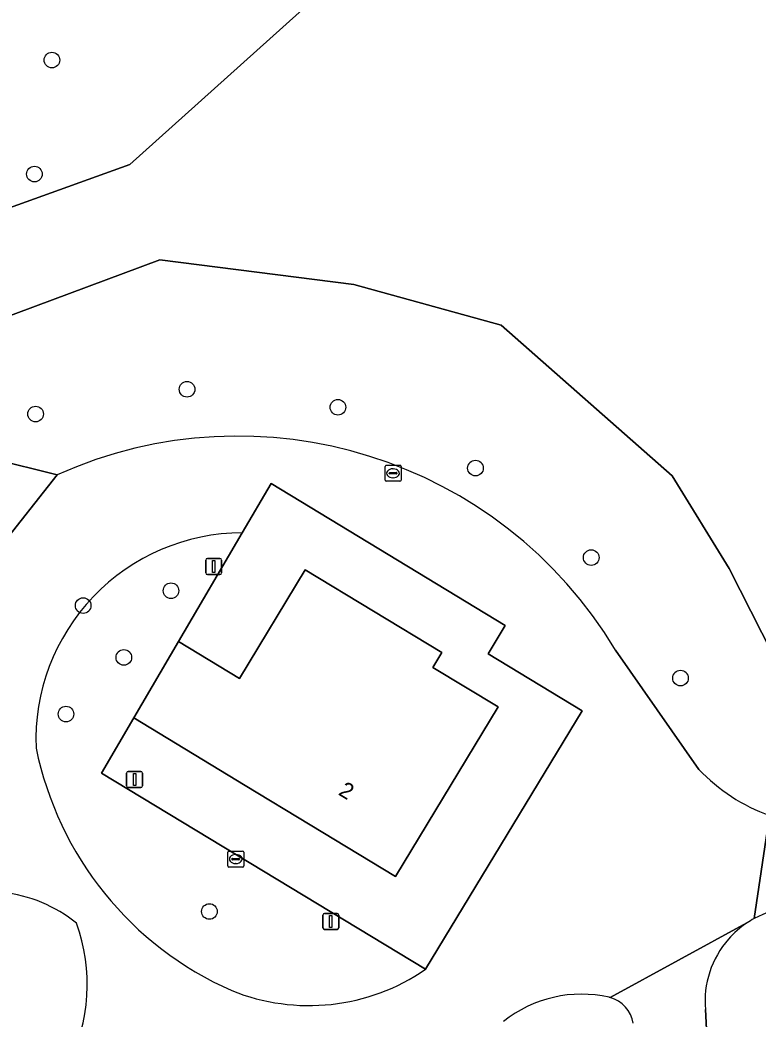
# Model space of a CAD drawing. Extents: x 157132 to 159279, y 384991 to 386650.
# Drawn here: x 158963.1 to 159009.3, y 385274.6 to 385337.1 of the extents above; entities that cross this region are included whole.
import ezdxf

# ---------------------------------------------------------------- set-up
doc = ezdxf.new("R2010")
doc.units = 0
for name, color, linetype in [('IMGEO_Boom', 7, 'Continuous'), ('IMGEO_Erf', 7, 'Continuous'), ('IMGEO_Gemengd_bos', 7, 'Continuous'), ('IMGEO_Groenvoorziening', 7, 'Continuous'), ('IMGEO_Lichtmast', 7, 'Continuous'), ('IMGEO_Pand', 7, 'Continuous'), ('IMGEO_Pand_nummerreeks', 7, 'Continuous'), ('IMGEO_Rioolput', 7, 'Continuous'), ('IMGEO_Voetpad_halfverhard', 7, 'Continuous')]:
    doc.layers.add(name, color=color, linetype=linetype)

msp = doc.modelspace()

# ---------------------------------------------------------------- linework, layer by layer
at = {"layer": 'IMGEO_Boom'}
for centre in [(158965.128, 385334.634), (158964.034, 385327.492), (158973.584, 385314.015), (158983.029, 385312.89), (158964.106, 385312.467), (158991.637, 385309.08), (158998.879, 385303.476), (158972.581, 385301.402), (158967.084, 385300.47), (158969.63, 385297.223), (159004.469, 385295.927), (158966.009, 385293.676), (158974.984, 385281.314)]:
    msp.add_circle(centre, 0.489, dxfattribs=at)
at = {"layer": 'IMGEO_Erf'}
msp.add_lwpolyline([(158978.843, 385308.107), (158977.039, 385305.028), (158973.048, 385298.218), (158976.862, 385295.907), (158980.986, 385302.716), (158989.536, 385297.535), (158988.971, 385296.602), (158993.067, 385294.121), (158986.637, 385283.507), (158981.292, 385286.745), (158977.231, 385289.205), (158970.246, 385293.436), (158968.224, 385289.986), (158988.516, 385277.692), (158998.324, 385293.883), (158992.431, 385297.452), (158993.504, 385299.223)], close=True, dxfattribs=at)
at = {"layer": 'IMGEO_Gemengd_bos'}
for points in [[(159000.067, 385275.929), (159000, 385275.946)], [(159006.024, 385275.17), (159006.37, 385268.533), (159008.379, 385268.484), (159009.307, 385250), (159010.121, 385233.765), (159038.341, 385217.156), (159039.121, 385218.285)]]:
    msp.add_lwpolyline(points, dxfattribs=at)
for centre, radius, start, end in [((158961.135, 385273.769), 8.778, 50.89459, 84.10287), ((159011.929, 385275.665), 5.936, 94.97558, 118.8036), ((159012.182, 385275.253), 6.418, 119.01394, 123.60203), ((158956.077, 385276.751), 11.266, 332.96541, 19.87475), ((159011.896, 385275.706), 5.883, 123.71788, 138.74506), ((159011.933, 385275.676), 5.931, 138.76669, 184.89371), ((158998.28, 385268.26), 7.876, 77.38908, 128.39246), ((158999.536, 385274.017), 1.985, 8.53143, 74.48901)]:
    msp.add_arc(centre, radius, start, end, dxfattribs=at)
at = {"layer": 'IMGEO_Groenvoorziening'}
for points in [[(158962.808, 385385.31), (158927.58, 385336.09), (158925.528, 385331.856), (158955.073, 385313.584), (158959.489, 385317.515), (158971.873, 385322.123), (158984.027, 385320.568), (158993.243, 385318.034), (159003.957, 385308.587), (159007.514, 385302.784), (159015.678, 385286.714), (159042.69, 385289.202), (159041.339, 385291.519)], [(159007.514, 385302.784), (159003.957, 385308.587), (158993.243, 385318.034), (158984.027, 385320.568), (158971.873, 385322.123), (158959.489, 385317.515), (158955.073, 385313.584), (158958.196, 385311.653), (158961.42, 385309.659), (158965.458, 385308.659)], [(158968.224, 385289.986), (158970.246, 385293.436), (158973.048, 385298.218), (158977.039, 385305.028)], [(159015.678, 385286.714), (159007.514, 385302.784)], [(159000.4, 385297.684), (159005.617, 385290.211)], [(158988.516, 385277.692), (158968.224, 385289.986)]]:
    msp.add_lwpolyline(points, dxfattribs=at)
for points in [[(158974.969, 385377.175), (158969.67, 385375.217), (158966.329, 385370.263), (158969.324, 385358.052), (158963.794, 385345.265), (158951.929, 385334.09), (158951.929, 385329.597), (158952.044, 385325.335), (158955.961, 385323.031), (158970.015, 385328.099), (158981.42, 385338.352), (158985.452, 385352.753), (158981.996, 385373.259)], [(158981.42, 385338.352), (158970.015, 385328.099), (158955.961, 385323.031), (158952.044, 385325.335), (158951.929, 385329.597), (158951.929, 385334.09), (158963.794, 385345.265), (158969.324, 385358.052), (158966.329, 385370.263), (158969.67, 385375.217), (158974.969, 385377.175), (158981.996, 385373.259), (158985.452, 385352.753)]]:
    msp.add_lwpolyline(points, close=True, dxfattribs=at)
for centre, radius, start, end in [((158976.758, 385283.525), 27.558, 30.91768, 114.20816), ((158977.076, 385292.081), 12.947, 90.16542, 182.34533), ((158984.93, 385295.779), 21.216, 191.49664, 246.234), ((159014.068, 385298.31), 11.705, 223.7833, 249.8422), ((158981.212, 385288.312), 12.889, 247.98154, 304.51746)]:
    msp.add_arc(centre, radius, start, end, dxfattribs=at)
at = {"layer": 'IMGEO_Lichtmast'}
for p, q in [((158974.856, 385303.418), (158975.646, 385303.418)), ((158975.646, 385303.418), (158974.856, 385303.418)), ((158974.756, 385302.518), (158974.756, 385303.318)), ((158974.756, 385303.318), (158974.756, 385302.518)), ((158975.746, 385303.318), (158975.746, 385302.518)), ((158975.746, 385302.518), (158975.746, 385303.318)), ((158975.646, 385302.418), (158974.856, 385302.418)), ((158974.856, 385302.418), (158975.646, 385302.418)), ((158969.804, 385289.179), (158969.804, 385289.979)), ((158969.804, 385289.979), (158969.804, 385289.179)), ((158969.904, 385290.079), (158970.694, 385290.079)), ((158970.694, 385290.079), (158969.904, 385290.079)), ((158970.794, 385289.979), (158970.794, 385289.179)), ((158970.794, 385289.179), (158970.794, 385289.979)), ((158970.694, 385289.079), (158969.904, 385289.079)), ((158969.904, 385289.079), (158970.694, 385289.079)), ((158982.087, 385280.292), (158982.087, 385281.092)), ((158982.087, 385281.092), (158982.087, 385280.292)), ((158982.187, 385281.192), (158982.977, 385281.192)), ((158982.977, 385281.192), (158982.187, 385281.192)), ((158983.077, 385281.092), (158983.077, 385280.292)), ((158983.077, 385280.292), (158983.077, 385281.092)), ((158982.977, 385280.192), (158982.187, 385280.192)), ((158982.187, 385280.192), (158982.977, 385280.192))]:
    msp.add_line(p, q, dxfattribs=at)
for points in [[(158975.176, 385303.293), (158975.326, 385303.293), (158975.326, 385302.543), (158975.176, 385302.543), (158975.176, 385303.293)], [(158970.224, 385289.954), (158970.374, 385289.954), (158970.374, 385289.204), (158970.224, 385289.204), (158970.224, 385289.954)], [(158982.507, 385281.067), (158982.657, 385281.067), (158982.657, 385280.317), (158982.507, 385280.317), (158982.507, 385281.067)]]:
    msp.add_lwpolyline(points, dxfattribs=at)
for centre, start, end in [((158974.856, 385303.318), 90, 180), ((158974.856, 385303.318), 90, 180), ((158975.646, 385303.318), 0, 90), ((158975.646, 385303.318), 360, 90), ((158974.856, 385302.518), 180, 270), ((158974.856, 385302.518), 180, 270), ((158975.646, 385302.518), 270, 0), ((158975.646, 385302.518), 270, 0), ((158969.904, 385289.979), 90, 180), ((158969.904, 385289.979), 90, 180), ((158970.694, 385289.979), 0, 90), ((158970.694, 385289.979), 360, 90), ((158969.904, 385289.179), 180, 270), ((158969.904, 385289.179), 180, 270), ((158970.694, 385289.179), 270, 0), ((158970.694, 385289.179), 270, 0), ((158982.187, 385281.092), 90, 180), ((158982.187, 385281.092), 90, 180), ((158982.977, 385281.092), 0, 90), ((158982.977, 385281.092), 360, 90), ((158982.187, 385280.292), 180, 270), ((158982.187, 385280.292), 180, 270), ((158982.977, 385280.292), 270, 0), ((158982.977, 385280.292), 270, 0)]:
    msp.add_arc(centre, 0.1, start, end, dxfattribs=at)
at = {"layer": 'IMGEO_Pand'}
msp.add_lwpolyline([(158993.067, 385294.121), (158988.971, 385296.602), (158989.536, 385297.535), (158980.986, 385302.716), (158976.862, 385295.907), (158973.048, 385298.218), (158970.246, 385293.436), (158977.231, 385289.205), (158981.292, 385286.745), (158986.637, 385283.507)], close=True, dxfattribs=at)
at = {"layer": 'IMGEO_Rioolput'}
for p, q in [((158985.977, 385308.328), (158985.977, 385309.18)), ((158986.052, 385309.254), (158986.904, 385309.254)), ((158986.465, 385309.034), (158986.49, 385309.034)), ((158986.978, 385309.18), (158986.978, 385308.328)), ((158986.236, 385308.748), (158986.236, 385308.76)), ((158986.674, 385308.711), (158986.276, 385308.711)), ((158986.279, 385308.797), (158986.677, 385308.797)), ((158986.488, 385308.474), (158986.463, 385308.474)), ((158986.72, 385308.76), (158986.72, 385308.748)), ((158986.904, 385308.254), (158986.052, 385308.254)), ((158976.133, 385284.172), (158976.133, 385285.024)), ((158976.208, 385285.098), (158977.06, 385285.098)), ((158976.392, 385284.592), (158976.392, 385284.604)), ((158976.435, 385284.641), (158976.833, 385284.641)), ((158976.621, 385284.878), (158976.646, 385284.878)), ((158976.876, 385284.604), (158976.876, 385284.592)), ((158977.134, 385285.024), (158977.134, 385284.172)), ((158977.06, 385284.098), (158976.208, 385284.098)), ((158976.83, 385284.555), (158976.432, 385284.555)), ((158976.644, 385284.318), (158976.619, 385284.318))]:
    msp.add_line(p, q, dxfattribs=at)
for points in [[(158985.977, 385308.328), (158985.977, 385309.18)], [(158986.052, 385309.254), (158986.904, 385309.254)], [(158986.978, 385309.18), (158986.978, 385308.328)], [(158986.904, 385308.254), (158986.052, 385308.254)], [(158976.133, 385284.172), (158976.133, 385285.024)], [(158976.208, 385285.098), (158977.06, 385285.098)], [(158977.134, 385285.024), (158977.134, 385284.172)], [(158977.06, 385284.098), (158976.208, 385284.098)]]:
    msp.add_lwpolyline(points, dxfattribs=at)
for centre, radius, start, end in [((158986.054, 385309.178), 0.0765, 91.55205, 178.44795), ((158986.054, 385309.178), 0.0765, 91.55205, 178.44795), ((158986.902, 385309.178), 0.0765, 1.55205, 88.44795), ((158986.902, 385309.178), 0.0765, 1.55205, 88.44795), ((158986.276, 385308.757), 0.0403, 85.87752, 175.75265), ((158986.273, 385308.747), 0.0366, 178.93798, 274.71019), ((158986.677, 385308.754), 0.043, 264.86636, 352.45326), ((158986.681, 385308.759), 0.0386, 1.73085, 96.63898), ((158986.054, 385308.33), 0.0765, 181.55205, 268.44795), ((158986.054, 385308.33), 0.0765, 181.55205, 268.44795), ((158986.902, 385308.33), 0.0765, 271.55205, 358.44795), ((158986.902, 385308.33), 0.0765, 271.55205, 358.44795), ((158976.21, 385285.022), 0.0765, 91.55205, 178.44795), ((158976.21, 385285.022), 0.0765, 91.55205, 178.44795), ((158976.432, 385284.601), 0.0403, 85.87752, 175.75265), ((158976.429, 385284.591), 0.0366, 178.93798, 274.71019), ((158976.833, 385284.598), 0.043, 264.86636, 352.45326), ((158976.837, 385284.603), 0.0386, 1.73085, 96.63898), ((158977.058, 385285.022), 0.0765, 1.55205, 88.44795), ((158977.058, 385285.022), 0.0765, 1.55205, 88.44795), ((158976.21, 385284.174), 0.0765, 181.55205, 268.44795), ((158976.21, 385284.174), 0.0765, 181.55205, 268.44795), ((158977.058, 385284.174), 0.0765, 271.55205, 358.44795), ((158977.058, 385284.174), 0.0765, 271.55205, 358.44795)]:
    msp.add_arc(centre, radius, start, end, dxfattribs=at)
for centre, major_axis, ratio, start_param, end_param in [((158986.464, 385308.754), (-0.387, 0.002), 0.722429, 4.712389, 7.853982), ((158986.489, 385308.754), (-0.39, 0.002), 0.717154, 1.570796, 4.712389), ((158976.62, 385284.598), (-0.387, 0.002), 0.722429, 4.712389, 7.853982), ((158976.645, 385284.598), (-0.39, 0.002), 0.717154, 1.570796, 4.712389)]:
    msp.add_ellipse(centre, major_axis=major_axis, ratio=ratio, start_param=start_param, end_param=end_param, dxfattribs=at)
at = {"layer": 'IMGEO_Voetpad_halfverhard'}
for points in [[(158961.791, 385304.032), (158965.458, 385308.659), (158961.42, 385309.659), (158958.196, 385311.653), (158955.073, 385313.584), (158925.528, 385331.856)], [(158965.458, 385308.659), (158961.791, 385304.032)], [(158977.039, 385305.028), (158978.843, 385308.107), (158993.504, 385299.223), (158992.431, 385297.452), (158998.324, 385293.883), (158988.516, 385277.692)], [(159005.617, 385290.211), (159000.4, 385297.684)], [(159009.069, 385280.866), (159010.034, 385287.322)], [(159010.034, 385287.322), (159009.069, 385280.866)], [(159000, 385275.946), (159000.067, 385275.929), (159008.63, 385280.599)], [(159008.63, 385280.599), (159000.067, 385275.929)], [(159007.341, 385250), (159006.37, 385268.533), (159006.024, 385275.17)]]:
    msp.add_lwpolyline(points, dxfattribs=at)
for centre, radius, start, end in [((158976.758, 385283.525), 27.558, 30.91768, 114.20816), ((158977.076, 385292.081), 12.947, 90.16542, 182.34533), ((158984.93, 385295.779), 21.216, 191.49664, 246.234), ((159014.068, 385298.31), 11.705, 223.7833, 249.8422), ((158961.135, 385273.769), 8.778, 50.89459, 84.10287), ((159011.929, 385275.665), 5.936, 94.97558, 118.8036), ((159012.182, 385275.253), 6.418, 119.01394, 123.60203), ((158956.077, 385276.751), 11.266, 332.96541, 19.87475), ((159011.896, 385275.706), 5.883, 123.71788, 138.74506), ((159011.933, 385275.676), 5.931, 138.76669, 184.89371), ((158981.212, 385288.312), 12.889, 247.98154, 304.51746), ((158998.28, 385268.26), 7.876, 77.38908, 128.39246), ((158999.536, 385274.017), 1.985, 8.53143, 74.48901)]:
    msp.add_arc(centre, radius, start, end, dxfattribs=at)

# ---------------------------------------------------------------- texts
at = {"layer": 'IMGEO_Pand_nummerreeks'}
msp.add_text('2', height=1, rotation=328.79099, dxfattribs=at).set_placement((158983.002, 385288.655))

doc.saveas('drawing.dxf')
